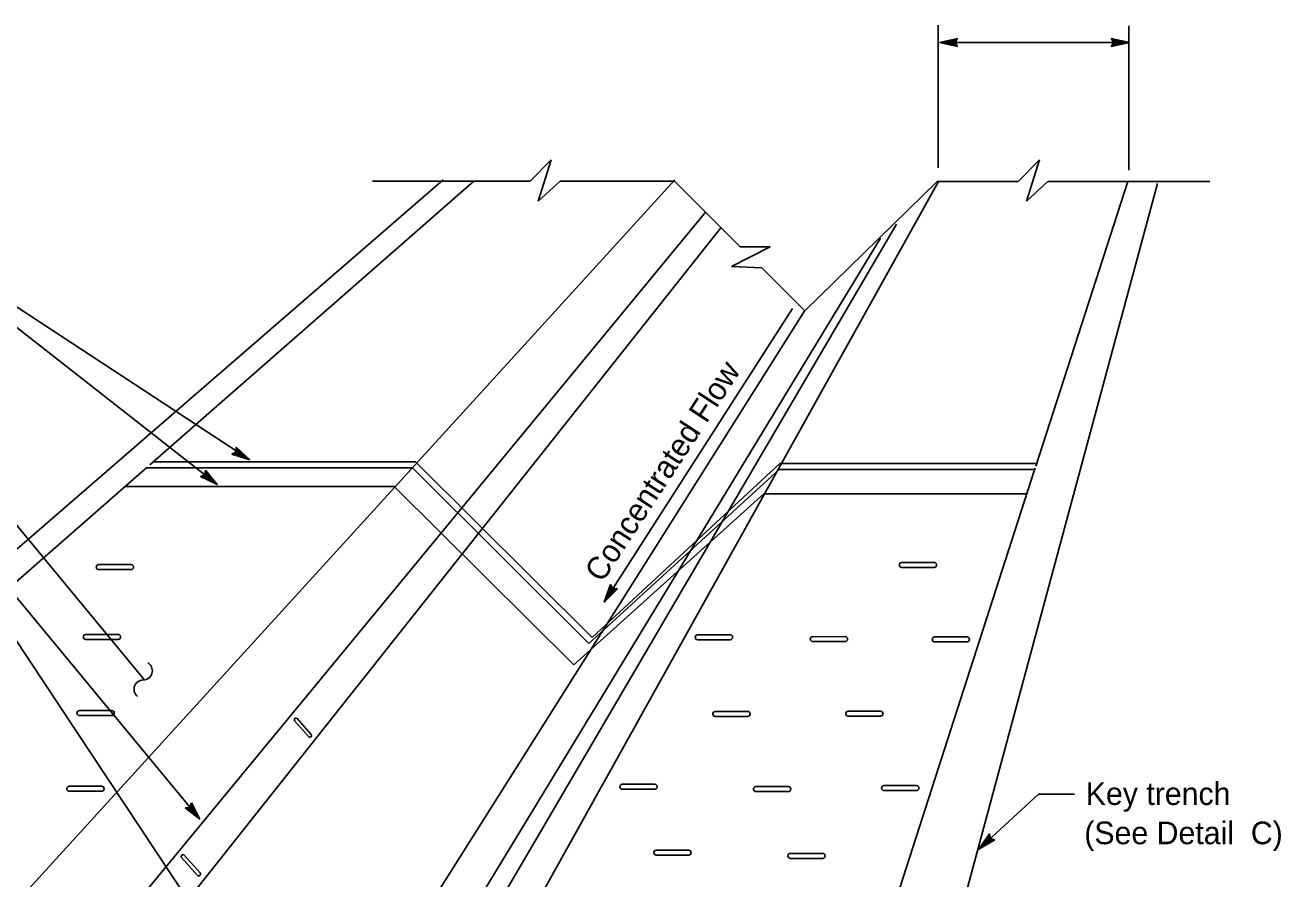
# Model space of a CAD drawing. Extents: x 6712486 to 6713732, y 1869200 to 1869925.
# Drawn here: x 6712663 to 6713009.5, y 1869385.4 to 1869620.8 of the extents above; entities that cross this region are included whole.
import ezdxf

# ---------------------------------------------------------------- set-up
doc = ezdxf.new("R2010")
doc.units = 0
for name, color, linetype in [('56 Stg 3 Anno', 7, 'Continuous'), ('57 Undefined', 7, 'Continuous'), ('60 Nongeo Data', 7, 'Continuous'), ('63 Undefined', 7, 'Continuous')]:
    doc.layers.add(name, color=color, linetype=linetype)

msp = doc.modelspace()

# ---------------------------------------------------------------- linework, layer by layer
at = {"layer": '56 Stg 3 Anno'}
for p, q in [((6712915.27, 1869615.97), (6712920.27, 1869617.08)), ((6712920.27, 1869614.85), (6712915.27, 1869615.97)), ((6712915.27, 1869615.97), (6712915.27, 1869615.97)), ((6712920.09, 1869615.15), (6712916.42, 1869615.97)), ((6712916.43, 1869615.97), (6712920.07, 1869616.78)), ((6712917.57, 1869615.97), (6712919.92, 1869616.49)), ((6712919.89, 1869615.45), (6712917.57, 1869615.97)), ((6712918.72, 1869615.97), (6712919.73, 1869616.19)), ((6712919.74, 1869615.74), (6712918.72, 1869615.97)), ((6712920.27, 1869617.08), (6712919.6, 1869615.97)), ((6712919.6, 1869615.97), (6712920.27, 1869614.85)), ((6712920.27, 1869617.08), (6712920.27, 1869617.08)), ((6712920.27, 1869614.85), (6712920.27, 1869614.85)), ((6712963.35, 1869615.97), (6712962.69, 1869617.09)), ((6712962.69, 1869617.09), (6712962.69, 1869617.09)), ((6712962.69, 1869617.09), (6712967.68, 1869615.97)), ((6712967.68, 1869615.97), (6712962.69, 1869614.86)), ((6712962.69, 1869614.86), (6712963.35, 1869615.97)), ((6712962.69, 1869614.86), (6712962.69, 1869614.86)), ((6712962.87, 1869616.79), (6712966.53, 1869615.97)), ((6712966.52, 1869615.97), (6712962.88, 1869615.16)), ((6712965.38, 1869615.97), (6712963.03, 1869615.45)), ((6712963.06, 1869616.49), (6712965.38, 1869615.97)), ((6712963.21, 1869616.2), (6712964.23, 1869615.97)), ((6712964.23, 1869615.97), (6712963.23, 1869615.75)), ((6712967.68, 1869615.97), (6712967.68, 1869615.97)), ((6712822.77, 1869461.73), (6712874.68, 1869542.63)), ((6712721.21, 1869503.13), (6712721.19, 1869504.43)), ((6712721.19, 1869504.43), (6712721.19, 1869504.43)), ((6712721.19, 1869504.43), (6712724.97, 1869500.98)), ((6712721.19, 1869504.08), (6712723.97, 1869501.55)), ((6712721.22, 1869503.73), (6712722.97, 1869502.12)), ((6712720.08, 1869502.5), (6712721.21, 1869503.13)), ((6712724.97, 1869500.98), (6712720.08, 1869502.5)), ((6712720.08, 1869502.5), (6712720.08, 1869502.5)), ((6712723.96, 1869501.55), (6712720.4, 1869502.66)), ((6712722.97, 1869502.12), (6712720.67, 1869502.84)), ((6712721.97, 1869502.7), (6712720.99, 1869503)), ((6712721.2, 1869503.4), (6712721.97, 1869502.7)), ((6712724.97, 1869500.98), (6712724.97, 1869500.98)), ((6712707.18, 1869405.01), (6712708.46, 1869405.19)), ((6712711.19, 1869401.83), (6712707.18, 1869405.01)), ((6712707.18, 1869405.01), (6712707.18, 1869405.01)), ((6712710.45, 1869402.73), (6712707.53, 1869405.04)), ((6712709.74, 1869403.61), (6712707.85, 1869405.11)), ((6712709.01, 1869404.51), (6712708.21, 1869405.15)), ((6712708.46, 1869405.19), (6712708.9, 1869406.41)), ((6712708.54, 1869405.45), (6712709.01, 1869404.51)), ((6712708.68, 1869405.74), (6712709.74, 1869403.61)), ((6712708.79, 1869406.08), (6712710.46, 1869402.72)), ((6712708.9, 1869406.41), (6712708.9, 1869406.41)), ((6712708.9, 1869406.41), (6712711.19, 1869401.83)), ((6712711.19, 1869401.83), (6712711.19, 1869401.83))]:
    msp.add_line(p, q, dxfattribs=at)
for centre, radius, start, end in [((6712695.55, 1869442.74), 2.57, 283.3074, 60.1497), ((6712695.64, 1869437.68), 2.59, 80.6529, 231.1528)]:
    msp.add_arc(centre, radius, start, end, dxfattribs=at)
at = {"layer": '60 Nongeo Data'}
for p, q in [((6712914.9, 1869581.47), (6712914.9, 1869620.78)), ((6712967.53, 1869580.82), (6712967.53, 1869620.56)), ((6712915.27, 1869615.97), (6712967.68, 1869615.97)), ((6712525.01, 1869359), (6712778.34, 1869578.13)), ((6712592.16, 1869303.9), (6712842.3, 1869578.16)), ((6712697.41, 1869499.54), (6712786.81, 1869577.74)), ((6712757.6, 1869295.4), (6712915.04, 1869577.68)), ((6712916.52, 1869359), (6712975.47, 1869577.15)), ((6712967.22, 1869577.65), (6712941.88, 1869499.22)), ((6712716.02, 1869494.14), (6712615.77, 1869572.5)), ((6712724.97, 1869500.98), (6712615.77, 1869572.5)), ((6712664.82, 1869343.79), (6712850.81, 1869569.33)), ((6712674.37, 1869337.36), (6712854.97, 1869564.91)), ((6712772.67, 1869342.91), (6712903.42, 1869565.95)), ((6712761.77, 1869336.38), (6712898.99, 1869562.05)), ((6712704.43, 1869267.1), (6712878.15, 1869542.07)), ((6712695.74, 1869440.43), (6712612.7, 1869540.92)), ((6712707.85, 1869379.8), (6712619.78, 1869512.45)), ((6712711.19, 1869401.83), (6712619.78, 1869512.45)), ((6712542.99, 1869364.46), (6712696.56, 1869498.79)), ((6712941.44, 1869497.88), (6712898.16, 1869363.97)), ((6712941.69, 1869498.63), (6712941.48, 1869497.99)), ((6712913.8, 1869472.65), (6712904.85, 1869472.65)), ((6712683.22, 1869470.67), (6712692.23, 1869470.67)), ((6712692.23, 1869472.04), (6712683.28, 1869472.04)), ((6712904.79, 1869471.28), (6712913.8, 1869471.28)), ((6712688.66, 1869452.8), (6712679.7, 1869452.79)), ((6712857.5, 1869452.71), (6712848.55, 1869452.71)), ((6712889.23, 1869452.19), (6712880.28, 1869452.18)), ((6712922.89, 1869452.11), (6712913.93, 1869452.1)), ((6712679.64, 1869451.43), (6712688.66, 1869451.43)), ((6712848.49, 1869451.34), (6712857.5, 1869451.34)), ((6712880.21, 1869450.82), (6712889.23, 1869450.82)), ((6712913.87, 1869450.74), (6712922.89, 1869450.74)), ((6712686.92, 1869431.81), (6712677.97, 1869431.81)), ((6712862.35, 1869431.56), (6712853.39, 1869431.56)), ((6712899, 1869431.64), (6712890.05, 1869431.64)), ((6712677.91, 1869430.44), (6712686.92, 1869430.44)), ((6712737.34, 1869429.02), (6712741.28, 1869424.6)), ((6712741.95, 1869425.2), (6712738.04, 1869429.59)), ((6712853.33, 1869430.19), (6712862.35, 1869430.19)), ((6712889.99, 1869430.27), (6712899, 1869430.27)), ((6712684.11, 1869410.94), (6712675.15, 1869410.94)), ((6712836.71, 1869411.48), (6712827.75, 1869411.48)), ((6712873.56, 1869410.85), (6712864.61, 1869410.85)), ((6712908.92, 1869411.11), (6712899.97, 1869411.11)), ((6712675.09, 1869409.57), (6712684.11, 1869409.57)), ((6712827.69, 1869410.11), (6712836.71, 1869410.11)), ((6712864.55, 1869409.48), (6712873.56, 1869409.48)), ((6712899.91, 1869409.74), (6712908.92, 1869409.74)), ((6712926.12, 1869393.6), (6712942.58, 1869408.74)), ((6712942.58, 1869408.74), (6712952.56, 1869408.74)), ((6712846.08, 1869393.33), (6712837.12, 1869393.33)), ((6712706.14, 1869391.32), (6712710.51, 1869386.41)), ((6712711.26, 1869387.07), (6712706.91, 1869391.95)), ((6712837.06, 1869391.96), (6712846.08, 1869391.96)), ((6712874.05, 1869391.07), (6712883.07, 1869391.07)), ((6712883.07, 1869392.44), (6712874.11, 1869392.43))]:
    msp.add_line(p, q, dxfattribs=at)
for points in [[(6712758.88, 1869577.74), (6712802.37, 1869577.74)], [(6712810.58, 1869577.74), (6712842.15, 1869577.74), (6712860.33, 1869559.68)], [(6712866.22, 1869553.83), (6712878.09, 1869542.04), (6712914.62, 1869577.65), (6712937, 1869577.65)], [(6712945.2, 1869577.65), (6712989.84, 1869577.65)], [(6712698.39, 1869500.37), (6712770.72, 1869500.37), (6712819.48, 1869451.91)], [(6712696.55, 1869498.69), (6712769.89, 1869498.69), (6712818.57, 1869450.32)], [(6712818.57, 1869450.32), (6712871.06, 1869498.26), (6712941.54, 1869498.26)], [(6712819.48, 1869451.91), (6712871.23, 1869499.94), (6712942.15, 1869499.94)], [(6712690.7, 1869493.63), (6712764.83, 1869493.63), (6712814.35, 1869444.42)], [(6712814.35, 1869444.42), (6712866.85, 1869491.55), (6712939.5, 1869491.55)]]:
    msp.add_lwpolyline(points, dxfattribs=at)
for centre, radius, start, end in [((6712904.88, 1869471.96), 0.685, 92.5576, 270), ((6712913.8, 1869471.96), 0.686, 270, 90), ((6712683.31, 1869471.36), 0.685, 92.5576, 270), ((6712692.23, 1869471.36), 0.686, 270, 90), ((6712679.73, 1869452.11), 0.685, 92.5576, 270), ((6712688.66, 1869452.11), 0.686, 270, 90), ((6712848.58, 1869452.03), 0.685, 92.5576, 270), ((6712857.5, 1869452.03), 0.686, 270, 90), ((6712880.31, 1869451.5), 0.685, 92.5576, 270), ((6712889.23, 1869451.5), 0.686, 270, 90), ((6712913.96, 1869451.42), 0.685, 92.5576, 270), ((6712922.88, 1869451.42), 0.686, 270, 90), ((6712678, 1869431.12), 0.685, 92.5576, 270), ((6712686.92, 1869431.12), 0.686, 270, 90), ((6712853.42, 1869430.88), 0.685, 92.5576, 270), ((6712862.35, 1869430.88), 0.686, 270, 90), ((6712890.08, 1869430.96), 0.685, 92.5576, 270), ((6712899, 1869430.96), 0.686, 270, 90), ((6712737.72, 1869429.27), 0.45, 44.2481, 221.6905), ((6712741.61, 1869424.9), 0.45, 221.6905, 41.6905), ((6712675.18, 1869410.26), 0.685, 92.5576, 270), ((6712684.11, 1869410.26), 0.686, 270, 90), ((6712827.78, 1869410.8), 0.685, 92.5576, 270), ((6712836.71, 1869410.8), 0.686, 270, 90), ((6712864.64, 1869410.17), 0.685, 92.5576, 270), ((6712873.56, 1869410.17), 0.686, 270, 90), ((6712900, 1869410.43), 0.685, 92.5576, 270), ((6712908.92, 1869410.43), 0.686, 270, 90), ((6712837.15, 1869392.64), 0.685, 92.5576, 270), ((6712846.08, 1869392.64), 0.686, 270, 90), ((6712706.56, 1869391.6), 0.5, 44.2481, 221.6905), ((6712874.14, 1869391.75), 0.685, 92.5576, 270), ((6712883.06, 1869391.75), 0.686, 270, 90), ((6712710.88, 1869386.74), 0.5, 221.6905, 41.6905)]:
    msp.add_arc(centre, radius, start, end, dxfattribs=at)
at = {"layer": '63 Undefined'}
for p, q in [((6712802.37, 1869577.74), (6712808.18, 1869583.61)), ((6712808.18, 1869583.61), (6712804.54, 1869572.24)), ((6712937, 1869577.65), (6712942.9, 1869583.61)), ((6712942.9, 1869583.61), (6712939.26, 1869572.24)), ((6712804.54, 1869572.24), (6712810.58, 1869577.74)), ((6712939.26, 1869572.24), (6712945.2, 1869577.65)), ((6712868.52, 1869559.67), (6712857.88, 1869554.27)), ((6712860.33, 1869559.68), (6712868.52, 1869559.67)), ((6712857.88, 1869554.27), (6712866.22, 1869553.83)), ((6712712.77, 1869498.09), (6712712.77, 1869498.09)), ((6712711.4, 1869496.34), (6712711.4, 1869496.34)), ((6712716.02, 1869494.14), (6712716.02, 1869494.14)), ((6712824.54, 1869466.53), (6712824.54, 1869466.53)), ((6712826.41, 1869465.33), (6712826.41, 1869465.33)), ((6712822.77, 1869461.73), (6712822.77, 1869461.73)), ((6712929.05, 1869397.8), (6712929.05, 1869397.8)), ((6712926.12, 1869393.6), (6712926.12, 1869393.6)), ((6712930.56, 1869396.16), (6712930.56, 1869396.16))]:
    msp.add_line(p, q, dxfattribs=at)
for points in [[(6712712.77, 1869498.09), (6712716.02, 1869494.14), (6712711.4, 1869496.34), (6712711.72, 1869496.46), (6712715.1, 1869494.85), (6712712.72, 1869497.75), (6712712.68, 1869497.41), (6712714.2, 1869495.55), (6712712.04, 1869496.59), (6712712.36, 1869496.71), (6712713.3, 1869496.26), (6712712.64, 1869497.07), (6712712.6, 1869496.8), (6712711.4, 1869496.34), (6712712.6, 1869496.8)], [(6712826.41, 1869465.33), (6712822.77, 1869461.73), (6712824.54, 1869466.53), (6712824.69, 1869466.23), (6712823.39, 1869462.71), (6712826.06, 1869465.34), (6712825.72, 1869465.36), (6712824.01, 1869463.67), (6712824.84, 1869465.92), (6712824.99, 1869465.61), (6712824.64, 1869464.63), (6712825.38, 1869465.37), (6712825.11, 1869465.38), (6712824.54, 1869466.53), (6712825.11, 1869465.38)], [(6712930.56, 1869396.16), (6712926.12, 1869393.6), (6712929.05, 1869397.8), (6712929.12, 1869397.46), (6712926.97, 1869394.38), (6712930.23, 1869396.26), (6712929.9, 1869396.36), (6712927.82, 1869395.15), (6712929.19, 1869397.12), (6712929.26, 1869396.78), (6712928.67, 1869395.93), (6712929.57, 1869396.45), (6712929.31, 1869396.53), (6712929.05, 1869397.8), (6712929.31, 1869396.53)]]:
    msp.add_lwpolyline(points, close=True, dxfattribs=at)

# ---------------------------------------------------------------- texts
at = {"layer": '57 Undefined'}
msp.add_text('Concentrated Flow', height=6.2451, rotation=56.8199, dxfattribs=at).set_placement((6712822.23, 1869466.83))
at = {"layer": '60 Nongeo Data'}
for s, height, p in [('Key trench', 6.245, (6712955.64, 1869405.78)), ('(See Detail  C)', 6.2451, (6712955.23, 1869394.96))]:
    msp.add_text(s, height=height, dxfattribs=at).set_placement(p)

doc.saveas('drawing.dxf')
